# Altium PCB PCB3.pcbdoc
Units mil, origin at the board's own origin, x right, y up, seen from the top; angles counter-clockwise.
Board outline 4320.16 x 3744.64 mil, 2 copper layers (Top Layer, Bottom Layer); 75 components, 76 nets, 331 pads, 85 vias.
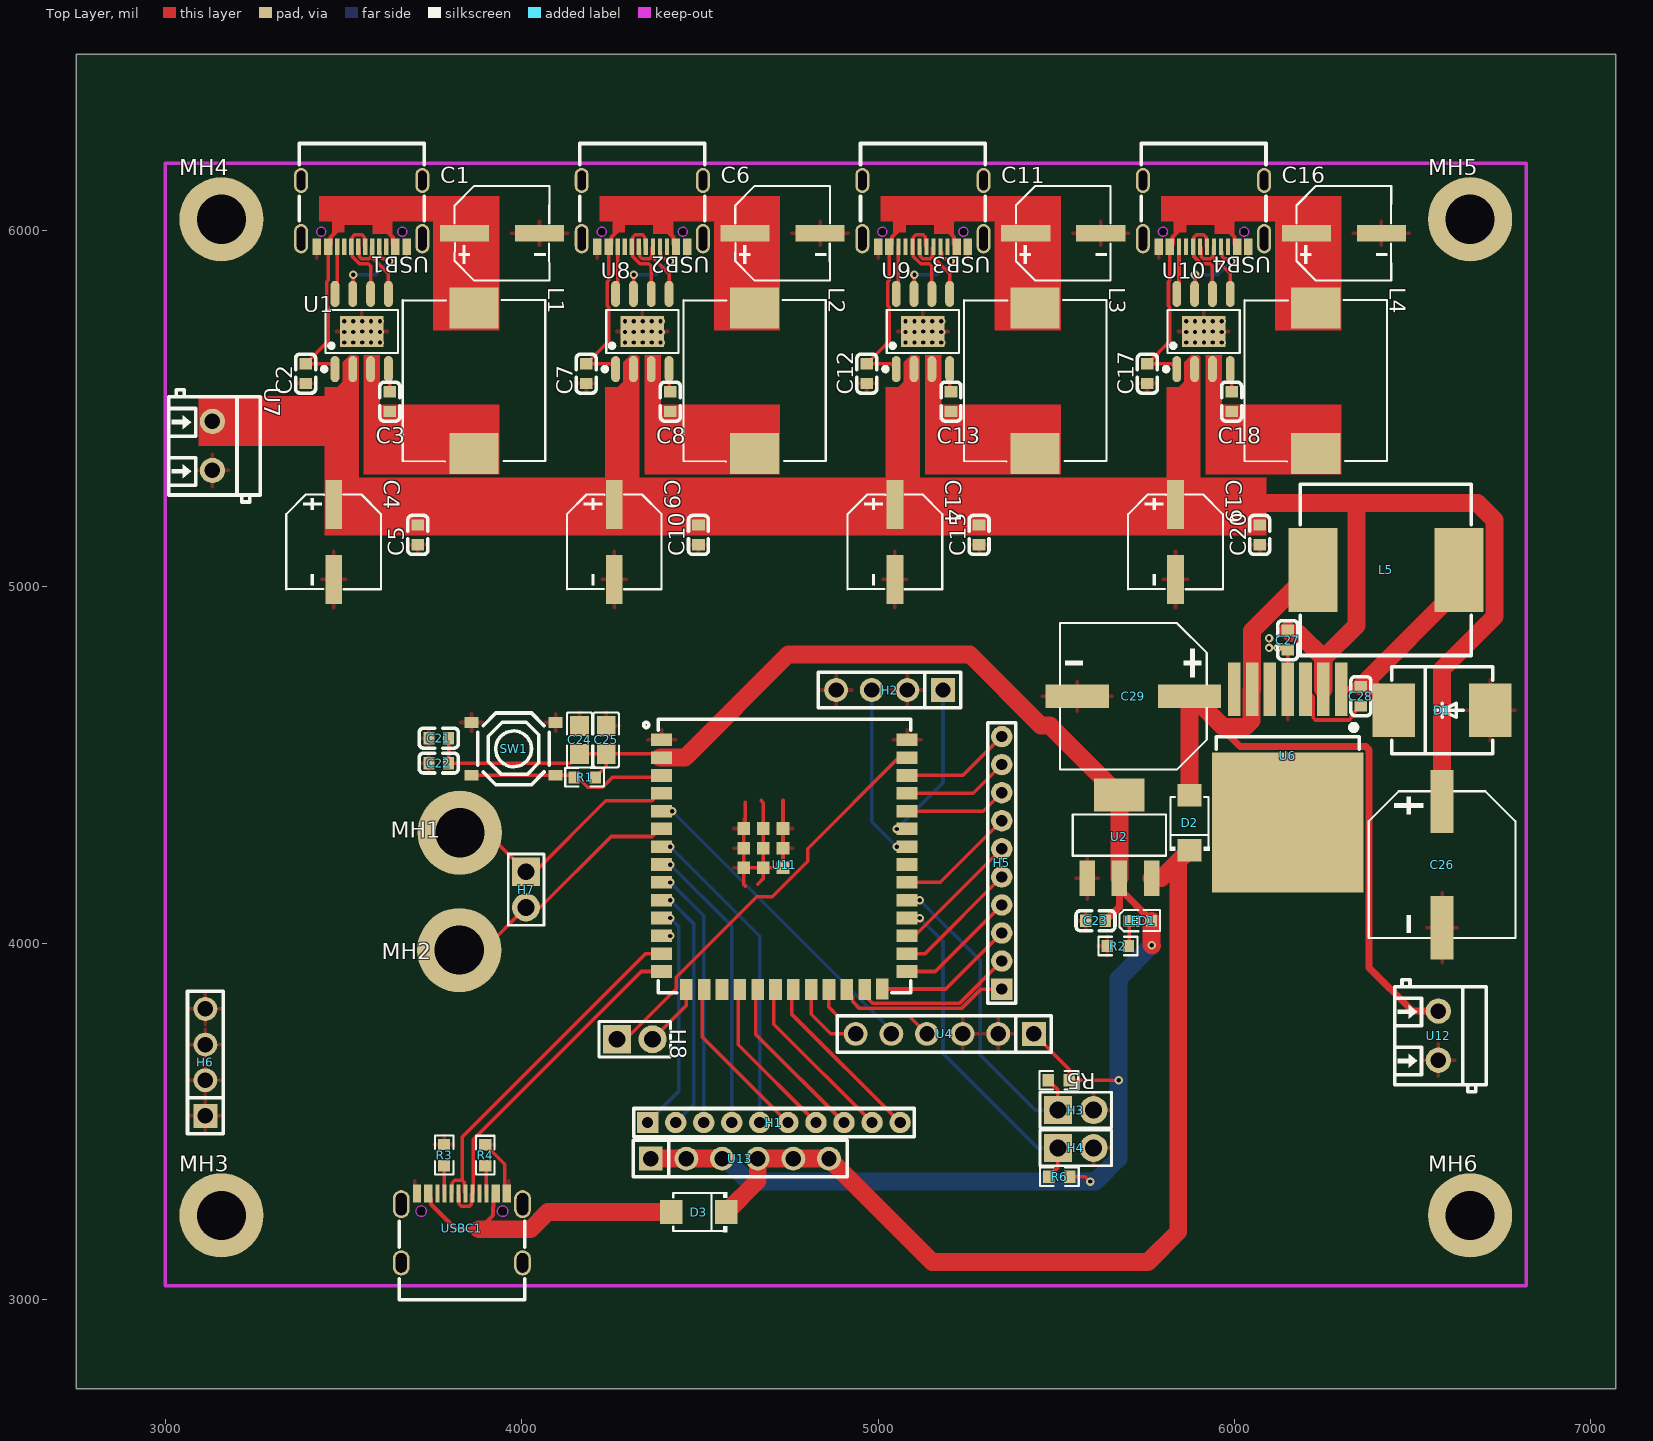
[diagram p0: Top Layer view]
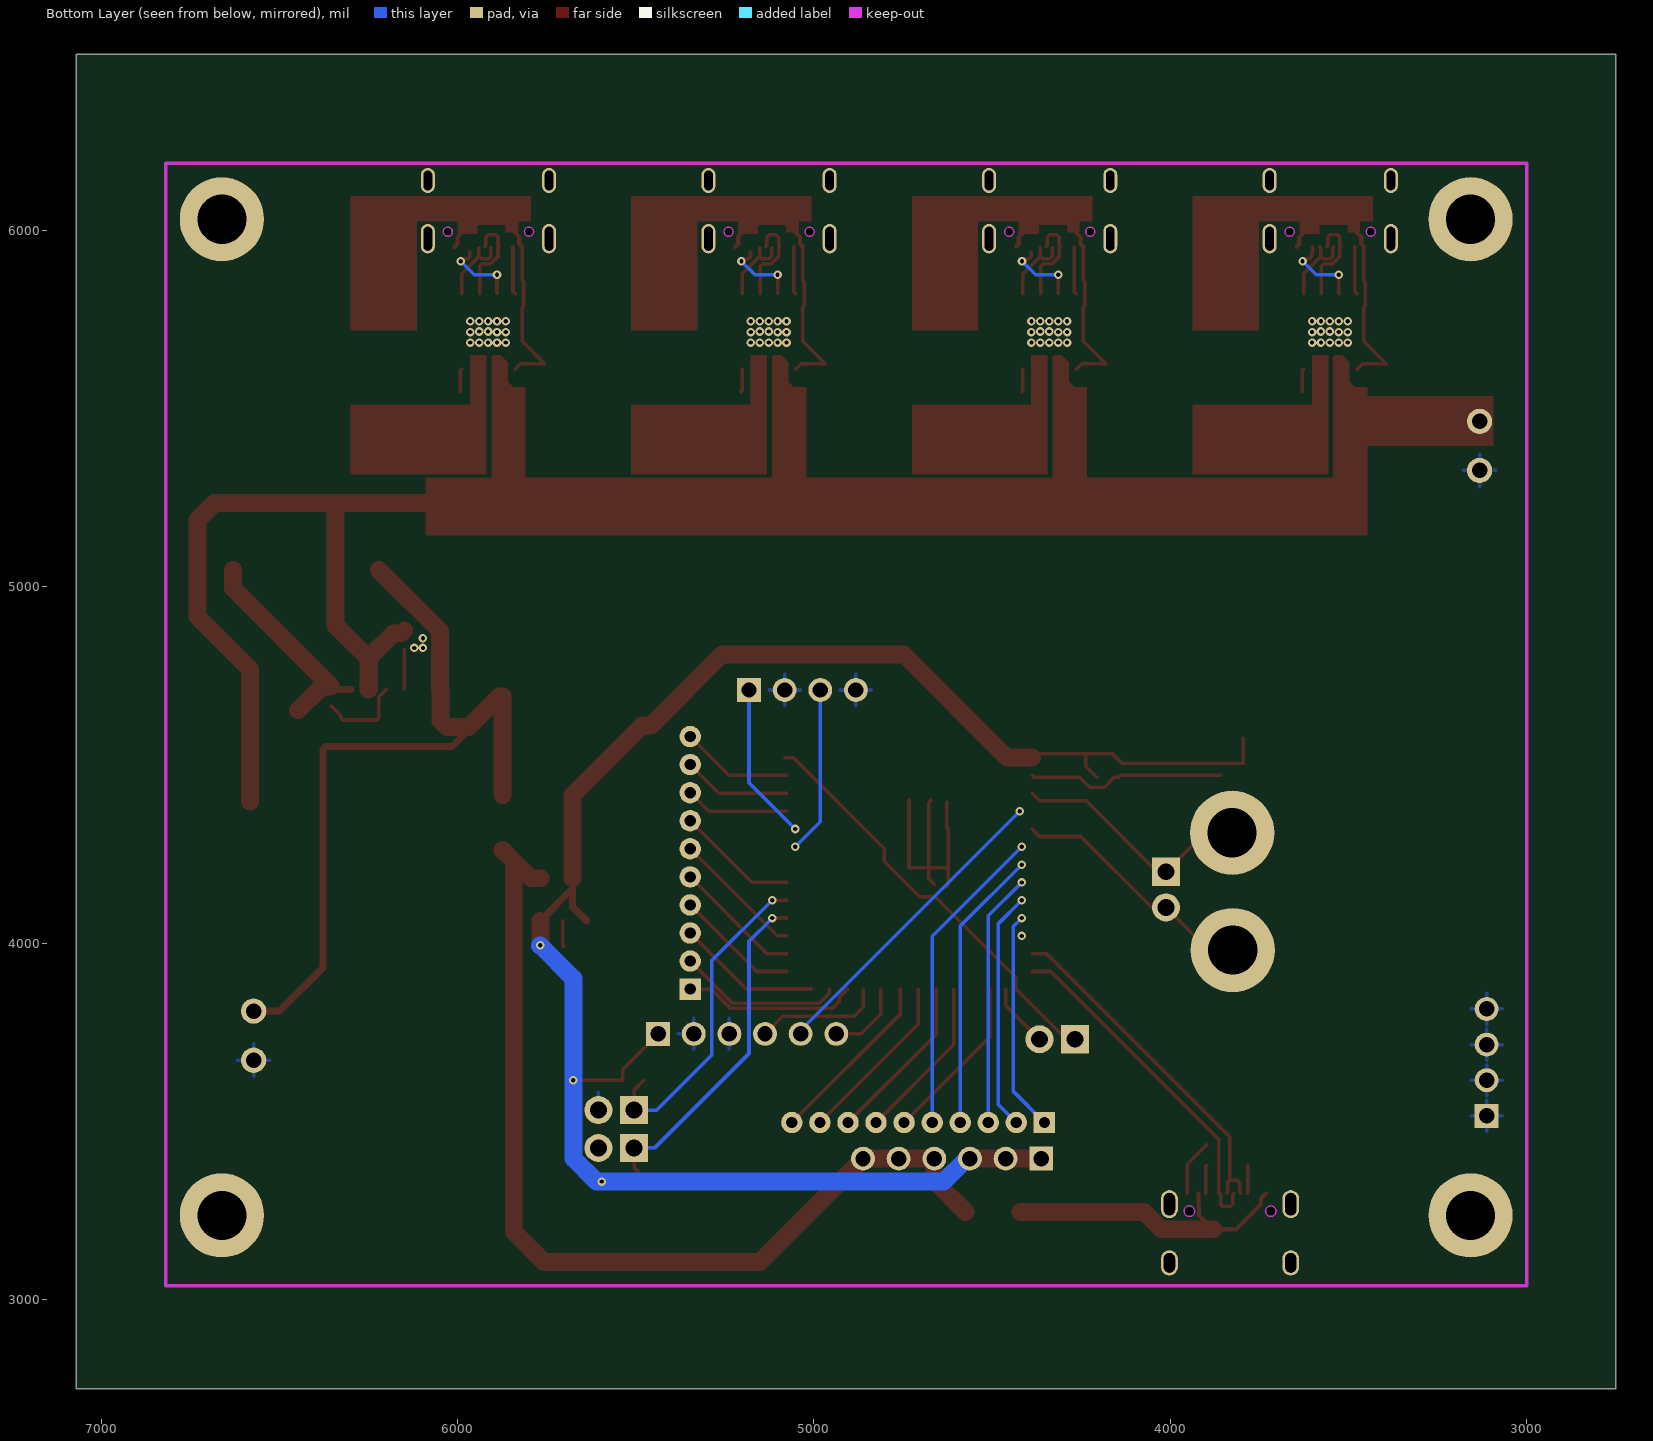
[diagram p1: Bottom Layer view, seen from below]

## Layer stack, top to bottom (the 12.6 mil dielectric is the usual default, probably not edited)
Top Layer: signal copper (thickness not stored)
Dielectric: dielectric 12.6, FR-4, Dk 4.8
Bottom Layer: signal copper (thickness not stored)

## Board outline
7070.16,2750 2750,2750 2750,6494.64 7070.16,6494.64

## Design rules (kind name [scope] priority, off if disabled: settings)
BoardOutlineClearance copperThickness1oz [All] p0: genericclearance=10 ignorepadtopadclearanceinfootprint=FALSE except(0: Arc-SplitContinuation Track-SplitContinuation SMDPad-SplitContinuation THPad-SplitContinuation Via-SplitContinuation Fill-SplitContinuation Poly-SplitContinuation Region-SplitContinuation Text-SplitContinuation; 6: Track-CutoutEdge SMDPad-CutoutEdge THPad-CutoutEdge Via-CutoutEdge Region-CutoutEdge; 11.8: Track-OutlineEdge SMDPad-OutlineEdge THPad-OutlineEdge Via-OutlineEdge Fill-OutlineEdge Region-OutlineEdge Poly-OutlineEdge Text-OutlineEdge Fill-CutoutEdge)
BoardOutlineClearance copperThickness2oz [All] p0: genericclearance=10 ignorepadtopadclearanceinfootprint=FALSE except(0: Arc-SplitContinuation Track-SplitContinuation SMDPad-SplitContinuation THPad-SplitContinuation Via-SplitContinuation Fill-SplitContinuation Poly-SplitContinuation Region-SplitContinuation Text-SplitContinuation; 6: Track-CutoutEdge SMDPad-CutoutEdge THPad-CutoutEdge Via-CutoutEdge Region-CutoutEdge; 11.8: Track-OutlineEdge SMDPad-OutlineEdge THPad-OutlineEdge Via-OutlineEdge Fill-OutlineEdge Region-OutlineEdge Poly-OutlineEdge Text-OutlineEdge Fill-CutoutEdge)
Clearance copperThickness1oz [(InNet('VCC') OR InNet('GND') OR InNet('$1N690') OR InNet('$1N965') OR InNet('DN_1') OR InNet('DP_1') OR InNet('CC1_1') OR InNet('CC2_1') OR InNet('VBUS_1') OR InNet('$1N1976') OR InNet('$1N1979') OR InNet('$1N2610') OR InNet('$1N2613') OR InNet('$1N3846') OR InNet('$1N3854') OR InNet('DN_2') OR InNet('DP_2') OR InNet('CC1_2') OR InNet('CC2_2') OR InNet('VBUS_2') OR InNet('DN_3') OR InNet('DP_3') OR InNet('CC1_3') OR InNet('CC2_3') OR InNet('VBUS_3') OR InNet('DN_4') OR InNet('DP_4') OR InNet('CC1_4') OR InNet('CC2_4') OR InNet('VBUS_4') OR InNet('USB_ESP_5V') OR InNet('USB_ESP_D-') OR InNet('USB_ESP_D+') OR InNet('+3V') OR InNet('BUTTON_2') OR InNet('TOUCH_2') OR InNet('TOUCH_1') OR InNet('BUTTON_1') OR InNet('+5V') OR InNet('MIC_SDK') OR InNet('RX') OR InNet('IO46') OR InNet('MIC_SCK') OR InNet('IO10') OR InNet('IO11') OR InNet('LED_1') OR InNet('LED_2') OR InNet('IO12') OR InNet('IO13') OR InNet('IO47') OR InNet('IO48') OR InNet('IO45') OR InNet('IO35') OR InNet('IO39') OR InNet('IO2') OR InNet('IO36') OR InNet('TX0') OR InNet('RX0') OR InNet('5V_BUCK') OR InNet('MIC_WS') OR InNet('TX') OR InNet('IO18') OR InNet('IO17') OR InNet('IO16') OR InNet('IO15') OR InNet('IO7') OR InNet('IO0') OR InNet('SDA_1') OR InNet('SCL_1') OR InNet('IO40') OR InNet('$1N7099') OR InNet('$1N7101') OR InNet('$1N7068') OR InNet('$1N7071') OR InNet('$1N7070') OR InNet('$1N7057'))] p1: gap=7 ignorepadtopadclearanceinfootprint=FALSE except(4: Track-Track; 6: Track-SMDPad SMDPad-SMDPad Track-THPad SMDPad-THPad THPad-THPad Track-Via SMDPad-Via THPad-Via Via-Via SMDPad-Fill THPad-Fill Via-Fill Fill-Fill Track-Region SMDPad-Region THPad-Region Via-Region Region-Region Track-Poly SMDPad-Poly THPad-Poly Via-Poly Fill-Poly Region-Poly Poly-Poly Track-Text SMDPad-Text THPad-Text Via-Text Fill-Text Region-Text Poly-Text Text-Text; 6.9: Track-Hole SMDPad-Hole THPad-Hole Via-Hole Fill-Hole Region-Hole Poly-Hole Text-Hole Sheet-Hole; 11.8: Track-Fill Fill-Region Track-Sheet SMDPad-Sheet THPad-Sheet Via-Sheet Fill-Sheet Region-Sheet Poly-Sheet Text-Sheet)
Clearance copperThickness2oz [All] p1: gap=7 ignorepadtopadclearanceinfootprint=FALSE except(6: Track-SMDPad SMDPad-SMDPad Track-THPad SMDPad-THPad THPad-THPad Track-Via SMDPad-Via THPad-Via Via-Via SMDPad-Fill THPad-Fill Via-Fill Fill-Fill Track-Region SMDPad-Region THPad-Region Via-Region Region-Region Track-Poly SMDPad-Poly THPad-Poly Via-Poly Fill-Poly Region-Poly Poly-Poly Track-Text SMDPad-Text THPad-Text Via-Text Fill-Text Region-Text Poly-Text Text-Text; 6.9: Track-Hole SMDPad-Hole THPad-Hole Via-Hole Fill-Hole Region-Hole Poly-Hole Text-Hole Sheet-Hole; 8: Track-Track; 11.8: Track-Fill Fill-Region Track-Sheet SMDPad-Sheet THPad-Sheet Via-Sheet Fill-Sheet Region-Sheet Poly-Sheet Text-Sheet)
DiffPairsRouting differentialPair [All] p1: maxuncoupledlength=10 minlimit=6 maxlimit=6 mostfreqgap=6 toplayer_minwidth=5 toplayer_prefwidth=10 toplayer_maxwidth=100 bottomlayer_minwidth=5 bottomlayer_prefwidth=10 bottomlayer_maxwidth=100
PasteMaskExpansion pasteMaskExpansion [All] p1: expansion=0
PlaneConnect innerPlane [All] p1: planeconnectstyle=Relief reliefexpansion=20 reliefentries=4 reliefconductorwidth=10 reliefairgap=10
PolygonConnect copperRegion [All] p1: connectstyle=Relief reliefentries=4 reliefconductorwidth=10 polygonreliefangle="90 Angle" airgapwidth=10
RoutingVias viaSize [All] p1: viastyle="Through Hole" holewidth=12.0078 minholewidth=11.811 maxholewidth=248.0314 width=24.0158 minwidth=19.685 maxwidth=393.7008
SolderMaskExpansion solderMaskExpansion [All] p1: useseparateexpansions=TRUE expansion=2 expansionbottom=2
Width copperThickness1oz [All] p1: maxlimit=100 minlimit=5 preferedwidth=10
Width copperThickness2oz [All] p1: maxlimit=100 minlimit=8 preferedwidth=10

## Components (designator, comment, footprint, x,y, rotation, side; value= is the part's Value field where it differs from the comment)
C1 "RVT100UF35V67RV0034" CAP-SMD_BD6.3-L6.6-W6.6-LS7.4-FD 3944.88,5992.21 r0 top
C2 "CC0603KRX7R9BB104" C0603 3393.7,5598.51 r90 top
C3 "UMK107BBJ225KA-T" C0603 3629.92,5519.77 r270 top
C4 "RVT100UF35V67RV0034" CAP-SMD_BD6.3-L6.6-W6.6-LS7.4-FD 3472.44,5126.06 r270 top
C5 "CC0603KRX7R9BB104" C0603 3708.66,5145.75 r90 top
C6 "RVT100UF35V67RV0034" CAP-SMD_BD6.3-L6.6-W6.6-LS7.4-FD 4732.28,5992.21 r0 top
C7 "CC0603KRX7R9BB104" C0603 4181.1,5598.51 r90 top
C8 "UMK107BBJ225KA-T" C0603 4417.32,5519.77 r270 top
C9 "RVT100UF35V67RV0034" CAP-SMD_BD6.3-L6.6-W6.6-LS7.4-FD 4259.84,5126.06 r270 top
C10 "CC0603KRX7R9BB104" C0603 4496.06,5145.75 r90 top
C11 "RVT100UF35V67RV0034" CAP-SMD_BD6.3-L6.6-W6.6-LS7.4-FD 5519.69,5992.21 r0 top
C12 "CC0603KRX7R9BB104" C0603 4968.5,5598.51 r90 top
C13 "UMK107BBJ225KA-T" C0603 5204.72,5519.77 r270 top
C14 "RVT100UF35V67RV0034" CAP-SMD_BD6.3-L6.6-W6.6-LS7.4-FD 5047.24,5126.06 r270 top
C15 "CC0603KRX7R9BB104" C0603 5283.46,5145.75 r90 top
C16 "RVT100UF35V67RV0034" CAP-SMD_BD6.3-L6.6-W6.6-LS7.4-FD 6307.09,5992.21 r0 top
C17 "CC0603KRX7R9BB104" C0603 5755.91,5598.51 r90 top
C18 "UMK107BBJ225KA-T" C0603 5992.13,5519.77 r270 top
C19 "RVT100UF35V67RV0034" CAP-SMD_BD6.3-L6.6-W6.6-LS7.4-FD 5834.65,5126.06 r270 top
C20 "CC0603KRX7R9BB104" C0603 6070.87,5145.75 r90 top
C21 "CC0603KRX7R9BB104" C0603 3767.28,4575.55 r0 top
C22 "CL10A106KP8NNNC" C0603 3767.28,4505.55 r0 top
C23 "CL10A226MP8NUNE" C0603 5610.24,4063.07 r0 top
C24 "CL21B225KAFNNNE" C0805 4162.28,4570.55 r270 top
C25 "CL21B225KAFNNNE" C0805 4237.28,4570.55 r270 top
C26 "VMME1001H181MV" CAP-SMD_BD10.0-L10.3-W10.3-FD 6582.68,4220.55 r270 top
C27 "CC0603KRX7R9BB104" C0603 6149.61,4850.47 r90 top
C28 "CC0603KRX7R9BB103" C0603 6354.96,4693.11 r270 top
C29 "RVT1H271M1010" CAP-SMD_BD10.0-L10.3-W10.3-FD-1 5716.54,4692.99 r180 top
D1 "B540C-13-F" SMC_L7.1-W6.2-LS8.1-RD 6582.68,4653.62 r0 top
D2 "S2MF_C908416" SMAF_L3.5-W2.6-LS4.7-RD 5874.02,4338.66 r90 top
D3 "S2MF_C908416" SMAF_L3.5-W2.6-LS4.7-RD 4497.28,3245.55 r180 top
H1 "HX PZ2.0-1x10P ZZ" HDR-TH_10P-P2.00-V-M-1 4707.69,3496.79 r0 top
H2 "PZ254V-11-04P" HDR-TH_4P-P2.54-V-M 5032.28,4710.55 r180 top
H3 "PZ254V-11-02P" HDR-TH_2P-P2.54-V-M 5554.82,3531.79 r0 top
H4 "PZ254V-11-02P" HDR-TH_2P-P2.54-V-M 5554.82,3425.5 r0 top
H5 "HX PZ2.0-1x10P ZZ" HDR-TH_10P-P2.00-V-M-1 5347.28,4225.55 r90 top
H6 "PZ254V-11-04P" HDR-TH_4P-P2.54-V-M 3112.28,3665.55 r90 top
H7 "PZ254V-11-02P" HDR-TH_2P-P2.54-V-M 4012.28,4150.55 r270 top
H8 "PZ254V-11-02P" HDR-TH_2P-P2.54-V-M 4317.28,3730.55 r0 top
L1 "SMMS1040-220M" IND-SMD_L11.5-W10.0_SMMS1040 3866.14,5578.82 r270 top
L2 "SMMS1040-220M" IND-SMD_L11.5-W10.0_SMMS1040 4653.54,5578.82 r270 top
L3 "SMMS1040-220M" IND-SMD_L11.5-W10.0_SMMS1040 5440.94,5578.82 r270 top
L4 "SMMS1040-220M" IND-SMD_L11.5-W10.0_SMMS1040 6228.35,5578.82 r270 top
L5 "MSS1210-334KED" IND-SMD_L12.0-W12.0_SLH1207S100MTT 6425.2,5047.32 r0 top
LED1 "XL-1608UGC-04" LED0603-RD_GREEN 5736.22,4063.07 r0 top
MH1 "M3_Hole" M3_Hole 3826.39,4310 r0 top
MH2 "M3_Hole" M3_Hole 3824.84,3980.59 r0 top
MH3 "M3_Hole" M3_Hole 3157.48,3236.3 r0 top
MH4 "M3_Hole" M3_Hole 3157.48,6031.58 r0 top
MH5 "M3_Hole" M3_Hole 6661.42,6031.58 r0 top
MH6 "M3_Hole" M3_Hole 6661.42,3236.3 r0 top
R1 "RC0603FR-0710KL" R0603 4176.6,4465.55 r0 top
R2 "RC0603FR-07330RL" R0603 5673.23,3992.21 r0 top
R3 "RC0603FR-075K1L" R0603 3782.28,3405.55 r90 top
R4 "RC0603FR-075K1L" R0603 3897.62,3405.21 r270 top
R5 "RC0603FR-0710KL" R0603 5507.28,3615.55 r0 top
R6 "RC0603FR-0710KL" R0603 5508.61,3344.85 r0 top
SW1 "TS-1187A-B-A-B" SW-SMD_4P-L5.1-W5.1-P3.70-LS6.5-TL_H1.5 3977.28,4545.55 r180 top
U1 "IP6520T_30W_PPS" ESOP-8_L4.9-W3.9-P1.27-LS6.0-BL-EP3.1 3551.18,5716.62 r0 top
U2 "AMS1117-3.3_C6186" SOT-223-3_L6.5-W3.4-P2.30-LS7.0-BR 5677.17,4299.29 r270 top
U4 "HB-PH3-25416PB2GOP" HDR-TH_6P-P2.54-V-M 5187.28,3745.55 r180 top
U6 "LM2678SX-5.0/NOPB" TO-263-7_L10.2-W8.6-P1.27-LS14.4-TL 6149.61,4525.55 r270 top
U7 "DB301V-3.5-2P-GN-S" CONN-TH_DB301V-3.5-2P-GN 3132.28,5395.55 r270 top
U8 "IP6520T_30W_PPS" ESOP-8_L4.9-W3.9-P1.27-LS6.0-BL-EP3.1 4338.58,5716.62 r0 top
U9 "IP6520T_30W_PPS" ESOP-8_L4.9-W3.9-P1.27-LS6.0-BL-EP3.1 5125.98,5716.62 r0 top
U10 "IP6520T_30W_PPS" ESOP-8_L4.9-W3.9-P1.27-LS6.0-BL-EP3.1 5913.39,5716.62 r0 top
U11 "ESP32-S3-WROOM-1U-N16R2" WIRELM-SMD_ESP32-S3-WROOM-1U 4737.28,4220.55 r0 top
U12 "DB301V-3.5-2P-GN-S" CONN-TH_DB301V-3.5-2P-GN 6572.28,3740.55 r270 top
U13 "HB-PH3-25416PB2GOP" HDR-TH_6P-P2.54-V-M 4612.28,3395.55 r0 top
USB1 "TYPE-C16PIN" USB-C-SMD_TYPE-C16PIN 3551.18,6047.32 r180 top
USB2 "TYPE-C16PIN" USB-C-SMD_TYPE-C16PIN 4338.58,6047.32 r180 top
USB3 "TYPE-C16PIN" USB-C-SMD_TYPE-C16PIN 5125.98,6047.32 r180 top
USB4 "TYPE-C16PIN" USB-C-SMD_TYPE-C16PIN 5913.39,6047.32 r180 top
USBC1 "TYPE-C-31-M-12" USB-C_SMD-TYPE-C-31-M-12 3832.28,3200.55 r0 top

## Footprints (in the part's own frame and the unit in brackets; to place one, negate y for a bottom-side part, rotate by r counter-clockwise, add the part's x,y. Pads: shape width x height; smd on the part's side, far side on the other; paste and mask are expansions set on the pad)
C0603 [mm]
  rect 0.8x0.9 smd: 1(-0.7,0) 2(0.7,0)
  silkscreen extent -1.39,-0.71 1.39,0.71
C0805 [mm]
  rect 1.41x1.35 smd: 1(-1,0) 2(1,0)
  silkscreen extent -1.96,-0.9 1.96,0.9
CAP-SMD_BD6.3-L6.6-W6.6-LS7.4-FD [mm]
  rect 3.5x1.2 smd: 1(-2.67,0) 2(2.67,0)
  silkscreen extent -3.38,-3.38 3.38,3.38
CAP-SMD_BD10.0-L10.3-W10.3-FD [mm]
  rect 4.5x1.65 smd: 1(-4.5,0) 2(4.5,0)
  silkscreen extent -5.23,-5.23 5.23,5.23
CAP-SMD_BD10.0-L10.3-W10.3-FD-1 [mm]
  rect 4.5x1.65 smd: 1(-4,0) 2(4,0)
  silkscreen extent -5.23,-5.23 5.23,5.23
CONN-TH_DB301V-3.5-2P-GN [mm]
  round 1.8 hole 1.1: 1(-1.75,0) 2(1.75,0)
  silkscreen extent -4,-3.1 4,3.4
ESOP-8_L4.9-W3.9-P1.27-LS6.0-BL-EP3.1 [mm]
  oval 0.63x1.865 smd: 1(-1.905,-2.682) 2(-0.635,-2.682) 3(0.635,-2.682) 4(1.905,-2.682) 5(1.905,2.682) 6(0.635,2.682) 7(-0.635,2.682) 8(-1.905,2.682)
  rect 3.1x2.2 smd: 9(0,0)
  silkscreen extent -2.82,-2.83 2.58,1.52
HDR-TH_2P-P2.54-V-M [mm]
  rect 2x2 hole 1.2: 1(-1.27,0)
  round 2 hole 1.2: 2(1.27,0)
  silkscreen extent -2.54,-1.27 2.54,1.27
HDR-TH_4P-P2.54-V-M [mm]
  rect 1.7x1.7 hole 1.1: 1(-3.81,0)
  round 1.7 hole 1.1: 2(-1.27,0) 3(1.27,0) 4(3.81,0)
  silkscreen extent -5.08,-1.27 5.08,1.27
HDR-TH_6P-P2.54-V-M [mm]
  rect 1.7x1.7 hole 1.1: 1(-6.35,0)
  round 1.7 hole 1.1: 2(-3.81,0) 3(-1.27,0) 4(1.27,0) 5(3.81,0) 6(6.35,0)
  silkscreen extent -7.6,-1.3 7.65,1.3
HDR-TH_10P-P2.00-V-M-1 [mil]
  rect 60x60 hole 31.5: 1(-354.33,0)
  round 60 hole 31.5: 2(-275.59,0) 3(-196.85,0) 4(-118.11,0) 5(-39.37,0) 6(39.37,0) 7(118.11,0) 8(196.85,0) 9(275.59,0) 10(354.33,0)
  silkscreen extent -394,-39 394,39
IND-SMD_L11.5-W10.0_SMMS1040 [mm]
  rect 2.924x3.5 smd: 1(-5.18,0) 2(5.18,0)
  silkscreen extent -5.74,-5.08 5.75,5.08
IND-SMD_L12.0-W12.0_SLH1207S100MTT [mm]
  rect 3.5x6 smd: 1(5.207,0) 2(-5.207,0)
  silkscreen extent -6.1,-6.1 6.1,6.1
LED0603-RD_GREEN [mm]
  rect 0.8x0.8 smd: 1(-0.799,-0.003) 2(0.799,0.003)
  silkscreen extent -1.49,-0.75 1.39,0.76
M3_Hole [mm]
  round 6 hole 3.5: 1(0,0)
R0603 [mil]
  rect 31.75x34.02 smd: 1(-29.66,0) 2(29.66,0)
  silkscreen extent -55,-26 55,26
SMAF_L3.5-W2.6-LS4.7-RD [mm]
  rect 1.6x1.7 smd: 1(-1.96,0) 2(1.96,0)
  silkscreen extent -2.01,-1.43 1.83,1.42
SMC_L7.1-W6.2-LS8.1-RD [mm]
  rect 3.03x3.82 smd: 1(-3.435,0) 2(3.435,0)
  silkscreen extent -3.6,-3.11 3.6,3.11
SOT-223-3_L6.5-W3.4-P2.30-LS7.0-BR [mm]
  rect 2.5x1.1 smd: 1(2.97,-2.3) 2(2.97,0) 3(2.97,2.3)
  rect 2.34x3.6 smd: 4(-2.97,0)
  silkscreen extent -1.57,-3.33 1.37,3.33
SW-SMD_4P-L5.1-W5.1-P3.70-LS6.5-TL_H1.5 [mm]
  rect 1x0.75 smd: 1(-3,1.875) 2(3,1.875) 3(-3,-1.875) 4(3,-1.875)
  silkscreen extent -2.55,-2.55 2.55,2.55
TO-263-7_L10.2-W8.6-P1.27-LS14.4-TL [mm]
  rect 3.81x0.9 smd: 1(-4.743,3.81) 2(-4.743,2.54) 3(-4.743,1.27) 4(-4.743,0) 5(-4.743,-1.27) 6(-4.743,-2.54) 7(-4.743,-3.81)
  rect 10x10.8 smd: 8(4.743,0)
  silkscreen extent -2.23,-5.09 -0.49,5.11
USB-C-SMD_TYPE-C16PIN [mm]
  oval 1x2.1 hole 0.6 slot 1.7 at 90 deg: 1(-4.32,1.787) 2(4.32,1.787)
  oval 1x1.8 hole 0.6 slot 1.4 at 90 deg: 3(-4.32,-2.362) 4(4.32,-2.362)
  rect 0.6x1.15 smd: A1B12(-3.2,2.362) A4B9(-2.4,2.362) B1A12(3.2,2.362) B4A9(2.4,2.362)
  rect 0.3x1.15 smd: A5(-1.25,2.362) A6(-0.25,2.362) A7(0.25,2.362) A8(1.25,2.362) B5(1.75,2.362) B6(0.75,2.362) B7(-0.75,2.362) B8(-1.75,2.362)
  Board Outline Layer circle w0.005: c2.89,1.288 r0.325
  Board Outline Layer circle w0.005: c-2.89,1.288 r0.325
  Board Outline Layer region: 2.565,1.288 2.597,1.429 2.687,1.542 2.818,1.605 2.962,1.605 3.093,1.542 3.183,1.429 3.215,1.288 3.215,1.288 3.183,1.147 3.093,1.034 2.962,0.971 2.818,0.971 2.687,1.034 2.597,1.147 2.565,1.288
  Board Outline Layer region: -3.215,1.288 -3.183,1.429 -3.093,1.542 -2.962,1.605 -2.818,1.605 -2.687,1.542 -2.597,1.429 -2.565,1.288 -2.565,1.288 -2.597,1.147 -2.687,1.034 -2.818,0.971 -2.962,0.971 -3.093,1.034 -3.183,1.147 -3.215,1.288
  Multi-Layer board cut-out: 2.565,1.288 2.597,1.429 2.687,1.542 2.818,1.605 2.962,1.605 3.093,1.542 3.183,1.429 3.215,1.288 3.215,1.288 3.183,1.147 3.093,1.034 2.962,0.971 2.818,0.971 2.687,1.034 2.597,1.147 2.565,1.288
  Multi-Layer board cut-out: -3.215,1.288 -3.183,1.429 -3.093,1.542 -2.962,1.605 -2.818,1.605 -2.687,1.542 -2.597,1.429 -2.565,1.288 -2.565,1.288 -2.597,1.147 -2.687,1.034 -2.818,0.971 -2.962,0.971 -3.093,1.034 -3.183,1.147 -3.215,1.288
  silkscreen extent -4.45,-5 4.45,0.52
USB-C_SMD-TYPE-C-31-M-12 [mm]
  oval 1.2x2 hole 0.8 slot 1.6 at 90 deg: 0(-4.325,1.706) 1(4.325,1.706)
  oval 1.2x1.8 hole 0.8 slot 1.4 at 90 deg: 2(4.325,-2.474) 3(-4.325,-2.474)
  rect 0.3x1.3 smd: A1(-3.35,2.474) A4(-2.55,2.474) A5(-1.25,2.474) A6(-0.25,2.474) A7(0.25,2.474) A8(1.25,2.474) A9(2.55,2.474) A12(3.35,2.474) B1(3.05,2.474) B4(2.25,2.474) B5(1.75,2.474) B6(0.75,2.474) B7(-0.75,2.474) B8(-1.75,2.474) B9(-2.25,2.474) B12(-3.05,2.474)
  Board Outline Layer circle w0.005: c-2.9,1.206 r0.375
  Board Outline Layer circle w0.005: c2.9,1.206 r0.375
  Board Outline Layer region: -2.525,1.206 -2.562,1.043 -2.666,0.912 -2.816,0.84 -2.983,0.84 -3.134,0.912 -3.238,1.043 -3.275,1.206 -3.275,1.206 -3.238,1.368 -3.134,1.499 -2.983,1.571 -2.816,1.571 -2.666,1.499 -2.562,1.368 -2.525,1.206
  Board Outline Layer region: 3.275,1.206 3.238,1.043 3.134,0.912 2.983,0.84 2.816,0.84 2.666,0.912 2.562,1.043 2.525,1.206 2.525,1.206 2.562,1.368 2.666,1.499 2.816,1.571 2.983,1.571 3.134,1.499 3.238,1.368 3.275,1.206
  Multi-Layer board cut-out: -2.525,1.206 -2.562,1.043 -2.666,0.912 -2.816,0.84 -2.983,0.84 -3.134,0.912 -3.238,1.043 -3.275,1.206 -3.275,1.206 -3.238,1.368 -3.134,1.499 -2.983,1.571 -2.816,1.571 -2.666,1.499 -2.562,1.368 -2.525,1.206
  Multi-Layer board cut-out: 3.275,1.206 3.238,1.043 3.134,0.912 2.983,0.84 2.816,0.84 2.666,0.912 2.562,1.043 2.525,1.206 2.525,1.206 2.562,1.368 2.666,1.499 2.816,1.571 2.983,1.571 3.134,1.499 3.238,1.368 3.275,1.206
  silkscreen extent -4.47,-5.09 4.47,0.49
WIRELM-SMD_ESP32-S3-WROOM-1U [mm]
  rect 1.5x0.9 smd: 1(-8.75,8.895) 2(-8.75,7.625) 3(-8.75,6.355) 4(-8.75,5.085) 5(-8.75,3.815) 6(-8.75,2.545) 7(-8.75,1.275) 8(-8.75,0.005) 9(-8.75,-1.265) 10(-8.75,-2.535) 11(-8.75,-3.805) 12(-8.75,-5.075) 13(-8.75,-6.345) 14(-8.75,-7.615) 27(8.75,-7.615) 28(8.75,-6.345) 29(8.75,-5.075) 30(8.75,-3.805) 31(8.75,-2.535) 32(8.75,-1.265) 33(8.75,0.005) 34(8.75,1.275) 35(8.75,2.545) 36(8.75,3.815) 37(8.75,5.085) 38(8.75,6.355) 39(8.75,7.625) 40(8.75,8.895)
  rect 0.9x1.5 smd: 15(-6.985,-8.895) 16(-5.715,-8.895) 17(-4.445,-8.895) 18(-3.175,-8.895) 19(-1.905,-8.895) 20(-0.635,-8.895) 21(0.635,-8.895) 22(1.905,-8.895) 23(3.175,-8.895) 24(4.445,-8.895) 25(5.715,-8.895) 26(6.985,-8.865)
  rect 0.9x0.9 smd: 41(-2.9,-0.225) 41(-2.9,1.175) 41(-2.9,2.575) 41(-1.5,-0.225) 41(-1.5,1.175) 41(-1.5,2.575) 41(-0.1,-0.225) 41(-0.1,1.175) 41(-0.1,2.575)
  silkscreen extent -10.04,-9.14 9.02,10.36

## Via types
v1: diameter 24.02, hole 12.01, Top Layer to Bottom Layer, 85 vias

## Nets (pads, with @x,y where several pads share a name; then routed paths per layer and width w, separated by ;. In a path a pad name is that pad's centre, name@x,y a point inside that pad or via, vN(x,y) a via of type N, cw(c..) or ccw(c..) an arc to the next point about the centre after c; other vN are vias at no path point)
5V_BUCK: C29.1 D2.2 L5.2 U6.6 U12.1 | length 2411.4
  Top Layer w20: C29.1 6015.37,4551.64 6368.83,4551.64 6378.19,4542.28 6378.19,3930.83 6499.57,3809.45 U12.1@6572.28,3809.45
  Top Layer w50: D2.2 C29.1 5882.38,4692.99 5969.06,4606.31 6030.16,4606.31 6048.31,4624.46 6048.31,4711 U6.6 6049.61,4876.73 L5.2
$1N690: C3.2 L1.2 U1.3
$1N965: C3.1 U1.4 | length 65.2
  Top Layer w10: U1.4 3629.92,5607.27 C3.1
$1N1976: C8.2 L2.2 U8.3
$1N1979: C8.1 U8.4 | length 65.2
  Top Layer w10: U8.4 4413.58,5551.07 C8.1
$1N2610: C13.2 L3.2 U9.3
$1N2613: C13.1 U9.4 | length 65.2
  Top Layer w10: U9.4 5200.98,5551.07 C13.1
$1N3846: C18.2 L4.2 U10.3
$1N3854: C18.1 U10.4 | length 65.2
  Top Layer w10: U10.4 5992.13,5607.27 C18.1
$1N7057: R1.1 SW1.1 SW1.2 U11.3 | length 556.5
  Top Layer w10: SW1.2 SW1.1 4140.76,4471.73 R1.1 4157.85,4465.55 4185.84,4437.56 4226.69,4437.56 4254.68,4465.55 4382.6,4465.55 U11.3@4387.79,4470.75
$1N7068: LED1.1 R2.2 | length 71.5
  Top Layer w10: R2.2 5704.75,3994.06 LED1.1
$1N7070: R4.2 USBC1.B5 | length 79.1
  Top Layer w10: R4.2 3901.18,3371.99 USBC1.B5
$1N7071: R3.1 USBC1.A5 | length 78.3
  Top Layer w10: R3.1 3783.07,3375.1 USBC1.A5
$1N7099: C28.2 U6.3 | length 245
  Top Layer w10: U6.3 6220.91,4691 6220.91,4632.75 6227.34,4626.31 6321.87,4626.31 6328.31,4632.75 6328.31,4638.9 C28.2
$1N7101: C28.1 D1.1 L5.1 U6.1 | length 607.9
  Top Layer w20: U6.1 C28.1@6346.59,4712.3
  Top Layer w50: D1.1 6380.39,4720.67 C28.1 6630.2,4995.91 L5.1
+3V: C21.2 C22.2 C23.2 C24.2 C25.2 LED1.2 R1.2 R5.2 R6.2 U2.2 U2.4 U4.1 U11.2 U13.1 U13.2 U13.3 | length 5242.8
  Top Layer w10: C21.2 C22.2 4136.65,4505.55 C24.2 C25.2 ; R1.2 4237.28,4496.57 C25.2 ; U11.2@4387.79,4520.75 4377.36,4531.18 C25.2 ; U4.1 5536.94,3645.89 R5.2 5675.05,3615.55 v1(5675.18,3615.42) ; R6.2 5581.73,3344.85 v1(5595.48,3331.1)
  Top Layer w20: C23.2 5677.17,4102.44 5677.17,4153.74 LED1.2
  Top Layer w50: U13.1 U13.2 U13.3 ; U11.2@4387.79,4520.75 4458.5,4520.75 4748.31,4810.55 5257.28,4810.55 5457.28,4610.55 5482.83,4610.55 U2.4 U2.2 ; LED1.2 5767.7,3994.63 v1(5768.33,3994)
  Bottom Layer w50: U13.3 4571.14,3395.55 4635.59,3331.1 v1(5595.48,3331.1) 5609.92,3331.1 5675.18,3396.36 v1(5675.18,3615.42) 5675.18,3900.86 v1(5768.33,3994)
+5V: D2.1 D3.1 U2.3 U13.4 U13.5 U13.6 | length 2700
  Top Layer w50: D3.1 4662.28,3333.39 U13.4 U13.5 U13.6 5152.28,3105.55 5757.28,3105.55 5842.28,3190.55 5842.28,4229.77 ; U2.3 5794.88,4182.37 5842.28,4229.77 ; D2.1 5842.28,4229.77
BUTTON_1: H3.1 R5.1 U11.31 | length 922.3
  Top Layer w10: U11.31@5076.77,4120.75 5117.09,4120.75 v1(5117.28,4120.55) ; R5.1 5504.82,3588.35 H3.1
  Bottom Layer w10: v1(5117.28,4120.55) 5287.28,3950.55 5287.28,3685.55 5441.05,3531.79 H3.1
BUTTON_2: H4.1 R6.1 U11.30 | length 971.2
  Top Layer w10: U11.30@5076.77,4070.75 5117.09,4070.75 v1(5117.28,4070.55) ; R6.1 5504.82,3370.73 H4.1
  Bottom Layer w10: v1(5117.28,4070.55) 5182.28,4005.55 5182.28,3690.55 5447.34,3425.5 H4.1
CC1_1: U1.7 USB1.A5 | length 230.6
  Top Layer w10: U1.7 3527.28,5823.33 v1(3527.28,5875.55) ; USB1.A5 3600.39,5942.08 3603.19,5939.28 3603.19,5927.13 3609.63,5920.69 3621.78,5920.69 v1(3628.79,5913.68)
  Bottom Layer w10: v1(3527.28,5875.55) 3590.66,5875.55 v1(3628.79,5913.68)
CC1_2: U8.7 USB2.A5 | length 212.8
  Top Layer w10: U8.7@4314.69,5823.33 v1(4314.69,5875.55) ; USB2.A5@4390.59,5939.28 4390.59,5927.13 4397.03,5920.69 4409.18,5920.69 v1(4416.19,5913.68)
  Bottom Layer w10: v1(4314.69,5875.55) 4378.06,5875.55 v1(4416.19,5913.68)
CC1_3: U9.7 USB3.A5 | length 212.8
  Top Layer w10: U9.7@5102.09,5823.33 v1(5102.09,5875.55) ; USB3.A5@5177.99,5939.28 5177.99,5927.13 5184.43,5920.69 5196.59,5920.69 v1(5203.59,5913.68)
  Bottom Layer w10: v1(5102.09,5875.55) 5165.46,5875.55 v1(5203.59,5913.68)
CC1_4: U10.7 USB4.A5 | length 212.8
  Top Layer w10: U10.7@5889.49,5823.33 v1(5889.49,5875.55) ; USB4.A5@5965.4,5939.28 5965.4,5927.13 5971.83,5920.69 5983.99,5920.69 v1(5990.99,5913.68)
  Bottom Layer w10: v1(5889.49,5875.55) 5952.86,5875.55 v1(5990.99,5913.68)
CC2_1: U1.8 USB1.B5 | length 134.6
  Top Layer w10: U1.8 3482.28,5828.33 USB1.B5
CC2_2: U8.8 USB2.B5 | length 134.6
  Top Layer w10: U8.8 4269.68,5828.33 USB2.B5
CC2_3: U9.8 USB3.B5 | length 134.6
  Top Layer w10: U9.8 5057.08,5828.33 USB3.B5
CC2_4: U10.8 USB4.B5 | length 134.6
  Top Layer w10: U10.8 5844.49,5828.33 USB4.B5
DN_1: U1.5 USB1.A7 USB1.B7 | length 220.7
  Top Layer w10: USB1.A7 3544.13,5951.52 3544.13,5927.13 3550.57,5920.69 3571.48,5920.69 3577.91,5927.13 ; USB1.B7 3577.91,5951.51 3577.91,5927.13 ; U1.5 3626.18,5878.86 3577.91,5927.13
DN_2: U8.5 USB2.A7 USB2.B7 | length 212.8
  Top Layer w10: USB2.A7@4331.53,5951.52 4331.53,5927.13 4337.97,5920.69 4358.88,5920.69 4365.31,5927.13 ; USB2.B7@4365.31,5951.51 4365.31,5927.13 ; U8.5 4413.58,5878.86 4365.31,5927.13
DN_3: U9.5 USB3.A7 USB3.B7 | length 212.8
  Top Layer w10: USB3.A7@5118.93,5951.52 5118.93,5927.13 5125.37,5920.69 5146.28,5920.69 5152.71,5927.13 ; USB3.B7@5152.71,5951.51 5152.71,5927.13 ; U9.5 5200.98,5878.86 5152.71,5927.13
DN_4: U10.5 USB4.A7 USB4.B7 | length 212.8
  Top Layer w10: USB4.A7@5906.34,5951.52 5906.34,5927.13 5912.77,5920.69 5933.68,5920.69 5940.12,5927.13 ; USB4.B7@5940.12,5951.51 5940.12,5927.13 ; U10.5 5988.39,5878.86 5940.12,5927.13
DP_1: U1.6 USB1.A6 USB1.B6 | length 264.8
  Top Layer w10: USB1.A6 3558.23,5957.1 3558.23,5981.5 3551.8,5987.94 3530.89,5987.94 3524.45,5981.5 3524.45,5957.11 USB1.B6 3524.45,5951.51 3524.45,5926.99 3544.76,5906.68 3569.29,5906.68 3576.18,5899.78 U1.6
DP_2: U8.6 USB2.A6 USB2.B6 | length 260.9
  Top Layer w10: USB2.B6 4311.85,5957.11 4311.85,5981.5 4318.29,5987.94 4339.2,5987.94 4345.63,5981.5 4345.63,5957.1 USB2.A6 ; USB2.B6@4311.85,5951.51 4311.85,5926.99 4332.16,5906.68 4356.69,5906.68 4363.58,5899.78 U8.6
DP_3: U9.6 USB3.A6 USB3.B6 | length 260.9
  Top Layer w10: USB3.B6 5099.25,5957.11 5099.25,5981.5 5105.69,5987.94 5126.6,5987.94 5133.03,5981.5 5133.03,5957.1 USB3.A6 ; USB3.B6@5099.25,5951.51 5099.25,5926.99 5119.56,5906.68 5144.09,5906.68 5150.98,5899.78 U9.6
DP_4: U10.6 USB4.A6 USB4.B6 | length 260.9
  Top Layer w10: USB4.B6 5886.66,5957.11 5886.66,5981.5 5893.09,5987.94 5914,5987.94 5920.44,5981.5 5920.44,5957.1 USB4.A6 ; USB4.B6@5886.66,5951.51 5886.66,5926.99 5906.97,5906.68 5931.49,5906.68 5938.39,5899.78 U10.6
GND: C1.2 C2.1 C4.2 C5.1 C6.2 C7.1 C9.2 C10.1 C11.2 C12.1 C14.2 C15.1 C16.2 C17.1 C19.2 C20.1 C21.1 C22.1 C23.1 C24.1 C25.1 C26.2 C27.1 C29.2 D1.2 H2.2 H2.4 H3.2 H4.2 H6.1 H6.2 H6.3 H6.4 R2.1 R3.2 R4.1 SW1.3 SW1.4 U1.9 U2.1 U4.2 U4.3 U6.4 U7.2 U8.9 U9.9 U10.9 U11.1 U11.40 U11.41 U12.2 USB1.A1B12 USB1.B1A12 USB2.A1B12 USB2.B1A12 USB3.A1B12 USB3.B1A12 USB4.A1B12 USB4.B1A12 USBC1.A1 USBC1.A12 USBC1.B1 USBC1.B12 | length 1051.8
  Top Layer w10: R4.1 3952.36,3380.13 USBC1.B1 ; 4627.28,4160.55 4623.1,4164.73 U11.41@4623.1,4211.69 ; 4627.28,4395.55 4627.28,4326.11 4623.1,4321.93 4623.1,4266.81 U11.41@4623.1,4211.69 ; 4662.28,4165.55 4678.22,4181.49 U11.41@4678.22,4211.69 ; 4672.28,4400.55 4678.22,4394.61 4678.22,4321.93 4678.22,4266.81 U11.41@4678.22,4211.69 ; 4733.34,4400.55 4733.34,4321.93 4733.34,4266.81 4733.34,4211.69 U11.41@4678.22,4211.69 ; U6.4 C27.1 ; U11.41@4623.1,4211.69 U11.41@4678.22,4211.69
  other v1: 6097.25,4828.7 6121.65,4828.7 6097.28,4855.55 3502.28,5685.55 3527.28,5685.55 3552.28,5685.55 3577.28,5685.55 3602.28,5685.55 4289.69,5685.55 4314.69,5685.55 4339.69,5685.55 4364.69,5685.55 4389.69,5685.55 5077.09,5685.55 5102.09,5685.55 5127.09,5685.55 5152.09,5685.55 5177.09,5685.55 5864.49,5685.55 5889.49,5685.55 5914.49,5685.55 5939.49,5685.55 5964.49,5685.55 3502.28,5714.94 3527.28,5714.94 3602.28,5714.94 4289.69,5714.94 4314.69,5714.94 4389.69,5714.94 5077.09,5714.94 5102.09,5714.94 5177.09,5714.94 5864.49,5714.94 5889.49,5714.94 5964.49,5714.94 3552.28,5716.62 3577.28,5716.62 4339.69,5716.62 4364.69,5716.62 5127.09,5716.62 5152.09,5716.62 5914.49,5716.62 5939.49,5716.62 3502.28,5745.55 3527.28,5745.55 3552.28,5745.55 3577.28,5745.55 3602.28,5745.55 4289.69,5745.55 4314.69,5745.55 4339.69,5745.55 4364.69,5745.55 4389.69,5745.55 5077.09,5745.55 5102.09,5745.55 5127.09,5745.55 5152.09,5745.55 5177.09,5745.55 5864.49,5745.55 5889.49,5745.55 5914.49,5745.55 5939.49,5745.55 5964.49,5745.55
IO0: H5.4 U11.27 | length 347.8
  Top Layer w10: U11.27@5076.77,3920.75 5160.59,3920.75 H5.4
IO2: H5.10 U11.38 | length 315.7
  Top Layer w10: U11.38@5076.77,4470.75 5238.15,4470.75 H5.10
IO7: H1.5 U11.7 | length 877.7
  Bottom Layer w10: v1(4417.28,4270.55) 4668.32,4019.51 H1.5
IO10: H1.7 U11.18 | length 464.1
  Top Layer w10: U11.18@4607.28,3870.36 4607.28,3715.31 H1.7
IO11: H1.8 U11.19 | length 476
  Top Layer w10: U11.19@4657.28,3870.36 4657.28,3744.05 H1.8
IO12: H1.9 U11.20 | length 487.9
  Top Layer w10: U11.20@4707.28,3870.36 4707.28,3772.79 H1.9
IO13: H1.10 U11.21 | length 499.8
  Top Layer w10: U11.21@4757.28,3870.36 4757.28,3801.53 H1.10
IO15: H1.4 U11.8 | length 795.1
  Bottom Layer w10: v1(4417.28,4220.55) 4589.58,4048.26 H1.4
IO16: H1.3 U11.9 | length 712.5
  Bottom Layer w10: v1(4417.28,4170.55) 4510.84,4076.99 H1.3
IO17: H1.2 U11.10 | length 671.5
  Bottom Layer w10: v1(4417.28,4120.55) 4482.28,4055.55 4482.28,3546.97 H1.2
IO18: H1.1 U11.11 | length 619.3
  Bottom Layer w10: H1.1 4440.28,3583.7 4440.28,4047.56 v1(4417.28,4070.55)
IO35: H5.5 U11.28 | length 359.7
  Top Layer w10: U11.28@5076.77,3970.75 5131.85,3970.75 H5.5
IO36: H5.6 U11.29 | length 371.7
  Top Layer w10: U11.29@5076.77,4020.75 5103.11,4020.75 H5.6
IO39: H5.7 U11.32 | length 342.1
  Top Layer w10: U11.32@5076.77,4170.75 5174.37,4170.75 H5.7
IO40: U11.33
IO45: H5.3 U11.26 | length 405.1
  Top Layer w10: U11.26@5007.28,3871.54 5190.12,3871.54 H5.3
IO46: H1.6 U11.16 | length 472.9
  Top Layer w10: U11.16@4507.28,3870.36 4507.28,3736.57 H1.6
IO47: H5.1 U11.24 | length 492
  Top Layer w10: U11.24@4907.28,3870.36 4928.58,3849.06 4928.58,3836.28 4947.85,3817.01 5234.15,3817.01 5287.5,3870.36 5346.42,3870.36 H5.1
IO48: H5.2 U11.25 | length 462.4
  Top Layer w10: U11.25@4957.28,3870.36 4957.28,3858.76 4985.02,3831.03 5228.35,3831.03 H5.2
LED_1: H2.1 U11.35 | length 443.8
  Bottom Layer w10: v1(5052.28,4320.55) 5182.28,4450.55 H2.1
LED_2: H2.3 U11.34 | length 469
  Bottom Layer w10: H2.3 4982.28,4340.55 v1(5052.28,4270.55)
MIC_SCK: U4.4 U11.23 | length 355.9
  Top Layer w10: U11.23 4862.28,3820.55 4887.28,3795.55 5087.28,3795.55 U4.4
MIC_SDK: U4.6 U11.22 | length 217.6
  Top Layer w10: U11.22 4812.28,3800.55 4867.28,3745.55 U4.6
MIC_WS: U4.5 U11.5 | length 879.7
  Bottom Layer w10: v1(4422.28,4370.55) 5037.28,3755.55 U4.5
RX: H8.2 U11.15 | length 179.2
  Top Layer w10: H8.2 4462.28,3825.55 U11.15
RX0: H5.8 U11.36 | length 291.9
  Top Layer w10: U11.36@5076.77,4370.75 5295.63,4370.75 H5.8
SCL_1: U11.17
SDA_1: U11.12
  other v1: 4417.28,4020.55
TOUCH_1: H7.1 MH1.1 U11.4 | length 697.9
  Top Layer w10: MH1.1 3902.84,4310 H7.1 4037.28,4200.55 4236.18,4399.45 4366.49,4399.45 U11.4@4387.79,4420.75
TOUCH_2: H7.2 MH2.1 U11.6 | length 703.8
  Top Layer w10: MH2.1 3892.32,3980.59 H7.2 4052.28,4100.55 4251.18,4299.45 4366.49,4299.45 U11.6@4387.79,4320.75
TX: H8.1 U11.39 | length 1181.9
  Top Layer w10: H8.1 4292.28,3730.55 4433.58,3871.85 4433.58,3904.44 4659.7,4130.55 4703.18,4130.55 4802.28,4229.66 4802.28,4265.55 5057.48,4520.75 U11.39
TX0: H5.9 U11.37 | length 303.8
  Top Layer w10: U11.37@5076.77,4420.75 5266.89,4420.75 H5.9
USB_ESP_5V: D3.2 USBC1.A4 USBC1.A9 USBC1.B4 USBC1.B9 | length 877
  Top Layer w12: USBC1.A4 3745.49,3284.36 3745.49,3267.41 3815.54,3197.36 3880.68,3197.36 3919.71,3236.38 3919.71,3259.1 3920.86,3260.26 USBC1.B4
  Top Layer w50: 3880.68,3197.36 4025.18,3197.36 4073.38,3245.55 D3.2
USB_ESP_D+: U11.14 USBC1.A6 USBC1.B6 | length 973.2
  Top Layer w10: USBC1.A6 3825.23,3295.17 3825.23,3267.82 3831.67,3261.39 3852.58,3261.39 3859.01,3267.82 3859.01,3295.16 USBC1.B6 3864.59,3300.74 3864.59,3450.26 4335.08,3920.75 U11.14@4387.79,3920.75
USB_ESP_D-: U11.13 USBC1.A7 USBC1.B7 | length 991.4
  Top Layer w10: USBC1.B7 3805.55,3300.76 3805.55,3328.1 3811.99,3334.53 3832.9,3334.53 ; USBC1.A7 3839.33,3300.75 3839.33,3328.1 3832.9,3334.53 ; U11.13@4387.79,3970.75 4347.48,3970.75 3832.9,3456.17 3832.9,3334.53
VBUS_1: C1.1 C2.2 L1.1 U1.1 USB1.A4B9 USB1.B4A9 | length 578.2
  Top Layer w10: USB1.B4A9 3456.69,5860.12 3452.8,5856.22 3452.8,5788.23 3456.69,5784.33 3456.69,5689.06 C2.2 3461.12,5626.07 U1.1
  Top Layer w12: USB1.B4A9 3464.39,5962.01 3464.39,5981.92 3482.28,5999.81 3482.28,6005.55 ; 3612.28,6010.55 3612.28,6007.6 3637.97,5981.92 3637.97,5962.01 USB1.A4B9
VBUS_2: C6.1 C7.2 L2.1 U8.1 USB2.A4B9 USB2.B4A9 | length 578.2
  Top Layer w10: USB2.B4A9 4244.09,5860.12 4240.2,5856.22 4240.2,5788.23 4244.09,5784.33 4244.09,5689.06 C7.2 4248.52,5626.07 U8.1
  Top Layer w12: USB2.B4A9 4251.8,5962.01 4251.8,5981.92 4269.69,5999.81 4269.69,6005.55 ; 4399.69,6010.55 4399.69,6007.6 4425.37,5981.92 4425.37,5962.01 USB2.A4B9
VBUS_3: C11.1 C12.2 L3.1 U9.1 USB3.A4B9 USB3.B4A9 | length 578.2
  Top Layer w10: USB3.B4A9 5031.49,5860.12 5027.6,5856.22 5027.6,5788.23 5031.49,5784.33 5031.49,5689.06 C12.2 5035.92,5626.07 U9.1
  Top Layer w12: USB3.B4A9 5039.19,5962.01 5039.19,5981.92 5057.09,5999.81 5057.09,6005.55 ; 5187.09,6010.55 5187.09,6007.6 5212.77,5981.92 5212.77,5962.01 USB3.A4B9
VBUS_4: C16.1 C17.2 L4.1 U10.1 USB4.A4B9 USB4.B4A9 | length 578.2
  Top Layer w10: USB4.B4A9 5818.9,5860.12 5815,5856.22 5815,5788.23 5818.9,5784.33 5818.9,5689.06 C17.2 5823.33,5626.07 U10.1
  Top Layer w12: USB4.B4A9 5826.6,5962.01 5826.6,5981.92 5844.49,5999.81 5844.49,6005.55 ; 5974.49,6010.55 5974.49,6007.6 6000.18,5981.92 6000.18,5962.01 USB4.A4B9
VCC: C4.1 C5.2 C9.1 C10.2 C14.1 C15.2 C19.1 C20.2 C26.1 C27.2 U1.2 U6.2 U7.1 U8.2 U9.2 U10.2 | length 2549.9
  Top Layer w50: C19.1 5839.02,5235.55 6342.28,5235.55 ; C27.2 6157.99,4869.65 6180.16,4869.65 6248.31,4801.5 6248.31,4713.6 U6.2 6249.61,4798.83 6342.28,4891.51 6342.28,5235.55 ; C26.1 6582.68,4768.98 6730.08,4916.38 6730.08,5187.76 6682.28,5235.55 6342.28,5235.55
pads on no net: MH3.1 MH4.1 MH5.1 MH6.1 U6.5 U6.7 U6.8 USB1.1 USB1.2 USB1.3 USB1.4 USB1.A8 USB1.B8 USB2.1 USB2.2 USB2.3 USB2.4 USB2.A8 USB2.B8 USB3.1 USB3.2 USB3.3 USB3.4 USB3.A8 USB3.B8 USB4.1 USB4.2 USB4.3 USB4.4 USB4.A8 USB4.B8 USBC1.0 USBC1.1 USBC1.2 USBC1.3 USBC1.A8 USBC1.B8

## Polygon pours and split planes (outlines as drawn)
GND on Bottom Layer (solid, remove dead copper, pour order 2): 3000,6189.06 6820.16,6189.06 6820.16,3039.45 3000,3039.45
GND on Top Layer (solid, remove dead copper, pour order 0): 3000,6189.06 6820.16,6189.06 6818.9,3039.45 3000,3039.45

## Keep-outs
Board Outline Layer:
  lines w10: 3000,3039.45 6818.9,3039.45 6818.9,6189.06 3000,6189.06 3000,3039.45

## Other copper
Top Layer:
  region net VCC: 3447.28,5305.55 6089.49,5305.55 6089.49,5145.43 3447.28,5145.43
  region net $1N690: 3557.28,5315.55 3937.28,5315.55 3937.28,5510.55 3602.28,5510.55 3602.28,5650.82 3557.28,5650.58
  region net $1N1976: 4344.69,5315.55 4724.69,5315.55 4724.69,5510.55 4389.69,5510.55 4389.69,5650.82 4344.69,5650.58
  region net $1N2610: 5132.09,5315.55 5512.09,5315.55 5512.09,5510.55 5177.09,5510.55 5177.09,5650.82 5132.09,5650.58
  region net $1N3846: 5919.49,5315.55 6299.49,5315.55 6299.49,5510.55 5964.49,5510.55 5964.49,5650.82 5919.49,5650.58
  region net VBUS_1: 3752.28,5720.55 3937.28,5720.55 3937.28,6095.55 3432.24,6095.55 3432.24,6025.55 3467.81,6025.55 3467.81,5995.55 3502.28,5995.55 3502.28,6015.42 3582.28,6015.42 3582.28,5990.55 3637.28,5990.55 3637.28,6025.55 3752.28,6025.55
  region net VBUS_2: 4539.69,5720.55 4724.69,5720.55 4724.69,6095.55 4219.65,6095.55 4219.65,6025.55 4255.21,6025.55 4255.21,5995.55 4289.69,5995.55 4289.69,6015.42 4369.69,6015.42 4369.69,5990.55 4424.69,5990.55 4424.69,6025.55 4539.69,6025.55
  region net VBUS_3: 5327.09,5720.55 5512.09,5720.55 5512.09,6095.55 5007.05,6095.55 5007.05,6025.55 5042.61,6025.55 5042.61,5995.55 5077.09,5995.55 5077.09,6015.42 5157.09,6015.42 5157.09,5990.55 5212.09,5990.55 5212.09,6025.55 5327.09,6025.55
  region net VBUS_4: 6114.49,5720.55 6299.49,5720.55 6299.49,6095.55 5794.45,6095.55 5794.45,6025.55 5830.01,6025.55 5830.01,5995.55 5864.49,5995.55 5864.49,6015.42 5944.49,6015.42 5944.49,5990.55 5999.49,5990.55 5999.49,6025.55 6114.49,6025.55
  region net VCC: 3517.28,5650.55 3537.28,5650.55 3542.28,5645.55 3542.28,5200.55 3447.28,5200.55 3447.28,5560.55 3482.28,5560.55 3497.28,5575.55 3497.28,5630.55
  region net VCC: 4304.69,5650.55 4324.69,5650.55 4329.69,5645.55 4329.69,5200.55 4234.69,5200.55 4234.69,5560.55 4269.69,5560.55 4284.69,5575.55 4284.69,5630.55
  region net VCC: 5092.09,5650.55 5112.09,5650.55 5117.09,5645.55 5117.09,5200.55 5022.09,5200.55 5022.09,5560.55 5057.09,5560.55 5072.09,5575.55 5072.09,5630.55
  region net VCC: 5879.49,5650.55 5899.49,5650.55 5904.49,5645.55 5904.49,5200.55 5809.49,5200.55 5809.49,5560.55 5844.49,5560.55 5859.49,5575.55 5859.49,5630.55
  region net VCC: 3094.03,5396.66 3540.53,5396.66 3540.53,5534.44 3094.03,5534.44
